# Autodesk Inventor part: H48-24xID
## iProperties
Shininess: 64.0
Length Units: 11272
Angle Units: 11279
Time Units: 11290
Mass Units: 11286
Length Display Precision: 3
Angle Display Precision: 2
Compacted: True
Part Number: H48-24xID
Document SubType Name: Modeling
Created: 2002-11
Designer: JBrentner
Material: Steel, High Strength Low Alloy
Description: Drill Bushing
Density: 0.0
Volumn: 0.0
Area: 0.0
PropertySet Name: Model Information
Control State: 0
Master: False
Checked Out: False
Stock: H-I.D.x0.75x0.375
Matl: STD
ANSI_SYM: H48-24xID
Author: JBrentner
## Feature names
1. Extrusion1
2. Extrusion2
3. Fillet1
4. Chamfer1
5. Chamfer2
6. Fillet2
